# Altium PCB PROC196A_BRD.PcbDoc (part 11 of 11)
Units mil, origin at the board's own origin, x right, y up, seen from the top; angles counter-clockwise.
Board outline 3346.45 x 4921.26 mil, 8 copper layers (Top Layer, GND1, SIG1, PWR1, PWR2, SIG2, GND2, Bottom Layer), stack 54.534 mil thick; 736 components, 498 nets, 3030 pads, 1279 vias.
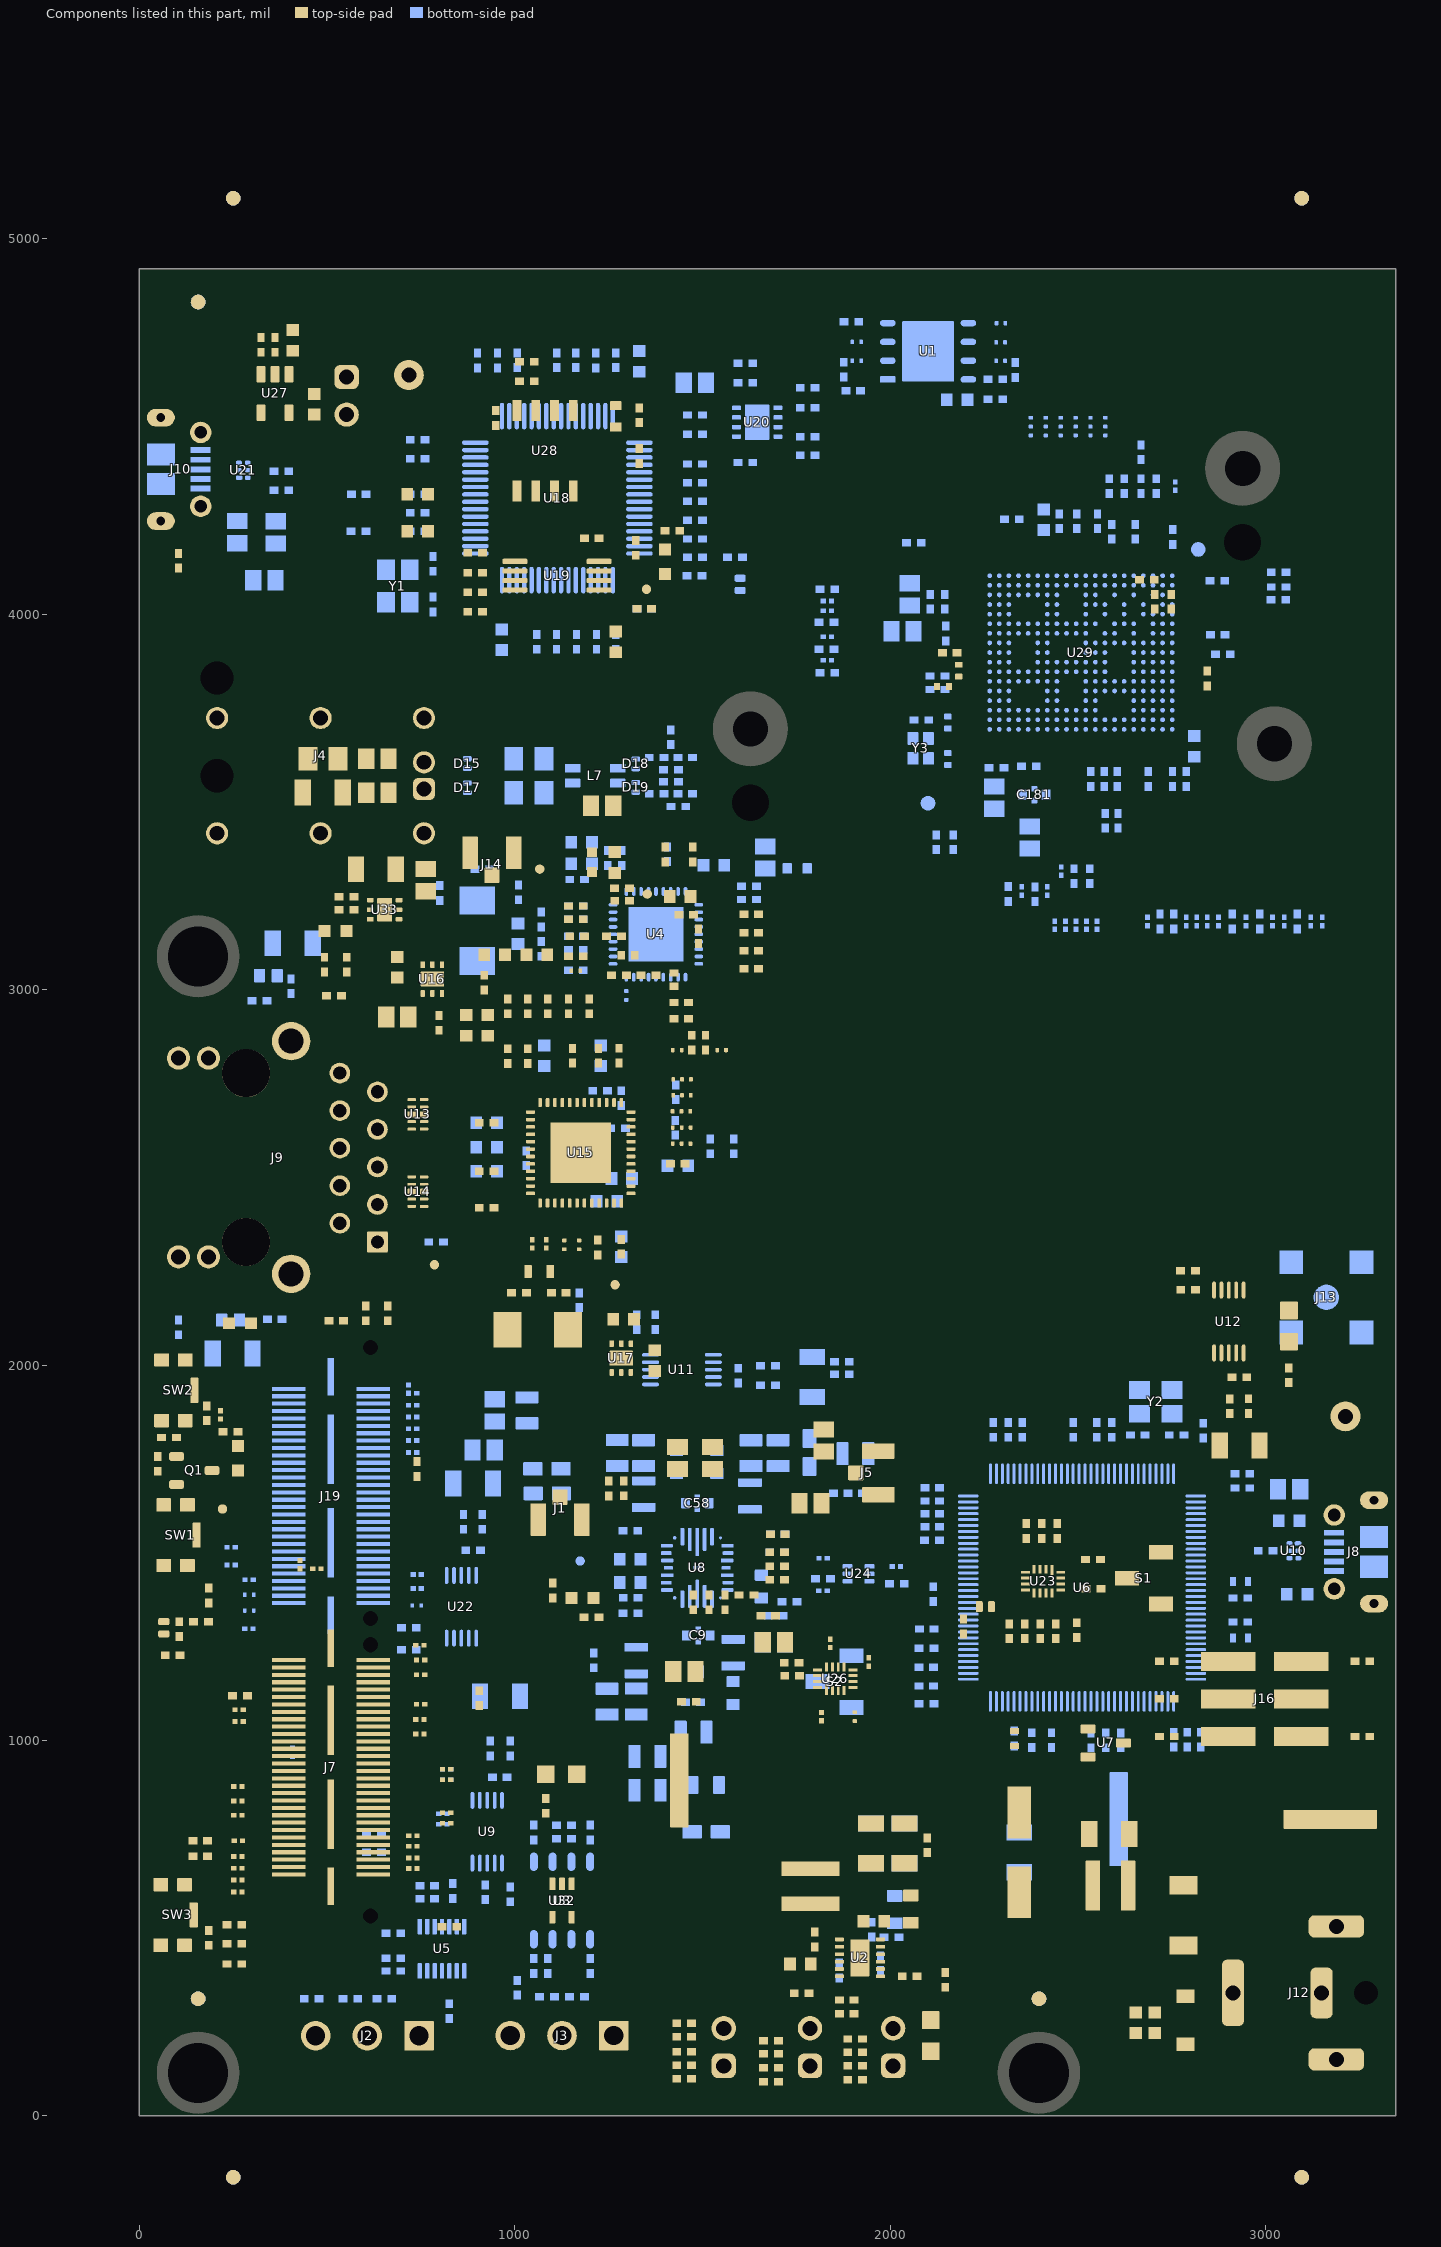
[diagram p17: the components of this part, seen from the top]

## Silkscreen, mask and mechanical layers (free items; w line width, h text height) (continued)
Bottom Overlay:
  circle w15: c2217,3665 r5
  circle w6: c2596.23,1933.67 r13.43
  circle w6: c657.29,3975.77 r13.43
  lines w10: 56.89,712.58 206.89,712.58 ; 56.89,507.81 56.89,1400.46 206.89,1400.46 206.89,507.81 56.89,507.81 ; 435.88,505.37 435.88,1118.29 537.35,1118.29 537.35,505.37 435.88,505.37
  text "FTDI_USB" at 323.96,4664.43 h30
  text "GND" at 786.99,4521.46 h30
  text "SOP4" at 2628.32,3368.81 h35 r270
  text "AUTO_ETH_JACK" at 629.91,3233.93 h30
  text "SOP3" at 2574.25,3225.81 h35
  text "CLKP_SMA" at 3248.2,2398.18 h30
  text "ETH_JACK" at 731.64,2386.93 h30 r270
  text "1V8" at 1833.2,2080.67 h30
  text "MIPI_CONN" at 326.39,1710.87 h30
  text "1V0" at 794.72,1690.41 h30
  text "1V0_FILT" at 986.29,1570.96 h30 r270
  text "XDS_USB" at 3286.71,1270.61 h30
  text "DBG_SPI" at 1974.28,1197.5 h30 r270
  text "1V2" at 832.48,1082.03 h30 r270
  text "SPI_MUX" at 1703,1012.81 h30 r270
  text "PMIC_SPI" at 1995,984.81 h30
  text "GND" at 2760.39,831.57 h30
  text "SL#" at 98.82,532.58 h30 r270
  text "ASSY REV:" at 465.64,527.97 h30 r270
  text "FY23-24/00616000201" at 301.83,458.31 h30 r270
  text "12V, >2.5A" at 2855.61,304.31 h30
  text ".Layer_Name" at 931.33,-846.68 h60
Top Paste:
  text ".Layer_Name" at 931.33,-846.68 h60
Bottom Paste:
  text ".Layer_Name" at 931.33,-846.68 h60
Top Solder:
  text ".Layer_Name" at 931.33,-846.68 h60
  text ".Layer_Name" at 931.33,-846.68 h60
Bottom Solder:
  text ".Layer_Name" at 931.33,-846.68 h60
Drill Guide:
  text ".Layer_Name" at 931.33,-846.68 h60
M1 Board Outline:
  lines w2: 0,0 3346.45,0 ; 0,0 0,-275.59 3346.45,-275.59 3346.45,0 ; 0,0 0,4921.25 ; 0,4921.26 3346.45,4921.26 ; 0,4921.25 0,5196.85 3346.45,5196.85 3346.45,4921.26 ; 3346.45,0 3346.45,4921.25
  text ".Layer_Name" at 468.07,-778 h30
M2 Board Dimensions:
  text ".Layer_Name" at 1011.75,-766.86 h30
M3 3D STEP Top:
  text ".Layer_Name" at 931.33,-846.68 h60
M4 3D STEP Bottom:
  text ".Layer_Name" at 931.33,-846.68 h60
M5 Assembly Top:
  lines w4: 1187.32,3003.74 1187.32,3009.92 1005.63,3009.92 1005.63,2948.6 1005.63,2891.43 1383.3,2891.43 1383.3,3018.25 1242.04,3018.25 1242.04,3012.6 ; 1955.2,51.3 1955.2,226.86 1853.52,226.86 1853.52,50.29 2295.24,50.29 2295.24,291.43 2164.08,291.43 2164.08,51.3 ; 1380.43,69.3 1501.44,69.3 1501.44,469.63 1380.43,469.63 1380.43,446.87 1380.43,69.3
  lines w10: 62.33,-918.36 6662.33,-918.36 ; 62.33,-715.02 6664.33,-715.02 ; 62.33,-511.69 62.33,-1121.69 4067.33,-1121.69 6664.33,-1121.69 6664.33,-511.69 62.83,-511.69 62.83,-1121.69 1638.33,-1121.69 ; 2527.33,-1121.69 2527.33,-511.69 ; 3794.33,-715.02 3794.33,-511.69 ; 4634.33,-715.02 4634.33,-511.69 ; 5256.33,-1128.19 5256.33,-925.36
  text "COMPONENTS MARKED 'DNP' SHOULD NOT BE POPULATED." at 3558.2,-220.46 h60
  text "ASSEMBLY VARIANT:" at 3557.7,-335.96 h60
  text ".VariantName" at 4593.7,-335.96 h60
  text "PCB VIEWED FROM TOP SIDE" at 125.83,-643.86 h60
  text "BOARD #:" at 2602.33,-643.86 h60
  text ".PRJ_Number" at 3147.83,-643.86 h60
  text "REV:" at 3992.33,-643.86 h60
  text ".PCB_Rev" at 4283.83,-643.86 h60
  text "SVN REV:" at 4830.33,-643.86 h60
  text ".VersionControl_RevNumber" at 5336.33,-643.86 h60
  text "TID #:" at 2602.33,-847.19 h60
  text ".TID" at 3147.83,-847.19 h60
  text "PLOT NAME =" at 125.83,-1052.53 h60
  text ".plot_File_Name" at 931.33,-1052.53 h60
  text "GENERATED    :" at 2604.33,-1052.53 h60
  text ".Print_Date" at 3473.83,-1052.53 h60
  text ".Print_Time" at 4202.83,-1052.53 h60
  text "TEXAS INSTRUMENTS" at 5467.33,-1052.53 h60
M6 Assembly Bottom:
  lines w4: 1087.19,738.71 1087.19,712.39 1176.38,712.39 1176.38,874.8 1087.19,874.8 1087.19,740.55
  lines w10: 61.83,-715.52 6663.83,-715.52 ; 63.83,-918.86 6663.83,-918.86 ; 1469.83,-1128.69 1469.83,-925.86 ; 2091.83,-715.52 2091.83,-512.19 ; 2931.83,-715.52 2931.83,-512.19 ; 4198.83,-1122.19 4198.83,-512.19 ; 5087.83,-1122.19 6663.33,-1122.19 6663.33,-512.19 61.83,-512.19 61.83,-1122.19 2658.83,-1122.19 6663.83,-1122.19 6663.83,-512.19
  text "COMPONENTS MARKED 'DNP' SHOULD NOT BE POPULATED." at 6456.33,-306.19 h60
  text ".VariantName" at 5412.33,-422.19 h60
  text "ASSEMBLY VARIANT:" at 6451.33,-422.19 h60
  text ".VersionControl_RevNumber" at 1389.83,-644.36 h60
  text "SVN REV:" at 1895.83,-644.36 h60
  text ".PCB_Rev" at 2442.33,-644.36 h60
  text "REV:" at 2733.83,-644.36 h60
  text ".PRJ_Number" at 3578.33,-644.36 h60
  text "BOARD #:" at 4123.83,-644.36 h60
  text "PCB VIEWED FROM BOTTOM SIDE" at 6600.33,-644.36 h60
  text ".TID" at 3578.33,-847.69 h60
  text "TID #:" at 4123.83,-847.69 h60
  text "TEXAS INSTRUMENTS" at 1258.83,-1053.03 h60
  text ".Print_Time" at 2523.33,-1053.03 h60
  text ".Print_Date" at 3252.33,-1053.03 h60
  text "GENERATED    :" at 4121.83,-1053.03 h60
  text ".plot_File_Name" at 5794.83,-1053.03 h60
  text "PLOT NAME =" at 6600.33,-1053.03 h60
M9 Title Sheet:
  drawing of 57 lines, arcs and shapes, not listed
  text "1" at 694.17,8048.31 h70
  text "2" at 3189.83,8048.31 h70
  text "3" at 5679.17,8048.31 h70
  text "4" at 8185.84,8048.31 h70
  text "5" at 10684.83,8048.31 h70
  text "6" at 13189.83,8048.31 h70
  text "A" at -462.17,6905.31 h70
  text "A" at 14337.83,6905.31 h70
  text "B" at -462.17,4525.31 h70
  text "B" at 14337.83,4525.31 h70
  text "C" at -462.17,2150.31 h70
  text "C" at 14337.83,2150.31 h70
  text "PROJECT TITLE:" at 11297.83,289.31 h45
  text "AWR2E44PEVM" at 11347.83,155.98 h70
  text "DESIGNED FOR:" at 11297.83,-11.69 h45
  text ".PRJ_Customer" at 11347.83,-151.69 h70
  text "D" at -462.17,-219.69 h70
  text "D" at 14337.83,-219.69 h70
  text "FILE NAME:" at 11297.83,-311.69 h45
  text ".PCB_File_Name_No_Path" at 11347.83,-431.69 h70
  text "Texas Instruments (TI) and/or its licensors do not warrant the accuracy or completeness of this specification" at 6328.33,-593.53 h45
  text "ENGINEER:" at 11297.83,-601.69 h45
  text "LAYOUT BY:" at 12802.83,-601.69 h45
  text "or any information contained therein. TI and/or its licensors do not warrant that this design will meet" at 6283.34,-706.19 h45
  text "MISTRAL" at 12853.33,-756.68 h70
  text "the specifications, will be suitable for your application or fit for any particular purpose, or will operate in" at 6283.34,-818.86 h45
  text "ALTIUM DESIGNER VERSION:" at 12802.83,-911.69 h45
  text "an implementation. TI and/or its licensors do not warrant that the design is production worthy. You should" at 6283.34,-931.52 h45
  text "completely validate and test your design implementation to confirm the system functionality for your application." at 6328.33,-1044.19 h45
  text ".print_Scale" at 11347.83,-1045.02 h70
  text ".Application_BuildNumber" at 12853.33,-1045.02 h70
  text "1" at 694.17,-1251.69 h70
  text "2" at 3189.83,-1251.69 h70
  text "3" at 5679.17,-1251.69 h70
  text "4" at 8185.84,-1251.69 h70
  text "5" at 10684.83,-1251.69 h70
  text "6" at 13189.83,-1251.69 h70
M10 Fab Notes:
  drawing of 259 lines, arcs and shapes, not listed
  text "DESIGN INFORMATION" at 12336.35,6367.98 h60
  text "MIN. TRACK WIDTH:" at 11691.79,6235.86 h60
  text "4" at 12788.03,6235.86 h60
  text "MIL" at 12942.79,6235.86 h60
  text "3.7" at 12734.95,6114.9 h60
  text "MIN. CLEARANCE:" at 11691.79,6111.73 h60
  text "MIL" at 12940,6111.81 h60
  text "10" at 12771.94,5990 h60
  text "MIN. VIA PAD SIZE:" at 11691.79,5987.61 h60
  text "MIL" at 12942.79,5987.61 h60
  text "MINIMUM ANNULAR RING" at 11327.35,5859.09 h60
  text "0.1mm (3.9MIL)" at 12386.79,5857.71 h60
  text "EXTERNAL" at 13140,5851.81 h60
  text "PER" at 11562.56,5739.36 h60
  text "IPC-D-275 CLASS 2 LEVEL C" at 11782.56,5739.35 h60
  text "MIL, HOLES" at 13270.79,5638.88 h60
  text "+/-" at 12878.33,5630.29 h60
  text "+/-" at 13732.33,5630.29 h60
  text "REGISTRATION TOLERANCES:" at 11362.56,5629.23 h60
  text "METAL" at 12562.33,5629.23 h60
  text "2" at 13138.53,5629.23 h60
  text "3" at 13971.53,5629.23 h60
  text "MIL" at 14087.79,5629.23 h60
  text "HOLE SIZE TOLERANCE (UNLESS OTHERWISE SPECIFIED):" at 11362.56,5530.91 h60
  text "+/-" at 13732.33,5528.04 h60
  text "3" at 13971.53,5526.98 h60
  text "MIL" at 14087.79,5526.98 h60
  text "MATERIAL:" at 11287.79,5389.33 h60
  text "FR-4 High Tg" at 12274.23,5260.81 h60
  text "X" at 12133,5256 h60
  text "FR-408" at 11708.79,5248.3 h60
  text "OTHER" at 13196.79,5248.3 h60
  text "64 MIL (1.63mm) +/-10%" at 12028.89,5105.27 h60
  text ".Total_Thickness" at 13606.73,5101.63 h50
  text "X" at 13190.46,5101 h60
  text "THICKNESS:" at 11362.56,5097.05 h60
  text "OTHER" at 13313.79,5097.05 h60
  text "+/-10%" at 13940.56,5093.91 h50
  text "TOLERANCE:" at 11362.56,4958.73 h60
  text "X" at 12210.79,4958.73 h60
  text "ANSI IPC-6012 TYPE 3 CLASS 2" at 12388.81,4958.73 h60
  text "OTHER +/-" at 12388.79,4814.54 h60
  text "BOW & TWIST:" at 11362.56,4669.35 h60
  text "X" at 12210.79,4669.35 h60
  text "ANSI IPC-6012 TYPE 3 CLASS 2" at 12388.81,4669.35 h60
  text "OTHER +/-" at 12388.79,4522.66 h60
  text "DRILLING:" at 11287.79,4392.04 h60
  text "NC_DRILL FILES" at 13048.79,4286.85 h60
  text "REFERENCE:" at 11362.56,4282.91 h60
  text "X" at 12019.79,4282.82 h60
  text "AS SHOWN" at 12197.79,4282.91 h60
  text "X" at 12920.79,4282.91 h60
  text "OTHER" at 13346.79,4140.66 h60
  text "PTH COPPER THICKNESS:" at 11362.24,4137.13 h60
  text "X" at 12501.47,4137.13 h60
  text "20-30 um" at 12629.47,4137.13 h60
  text "BOARD FINISH:" at 11287.79,3989.54 h60
  text "SILKSCREEN:" at 11443.01,3879.41 h60
  text "X" at 12400.79,3879.41 h60
  text "TOP" at 12517.79,3879.41 h60
  text "X" at 12910.79,3879.41 h60
  text "BOTTOM" at 13028.79,3879.41 h60
  text "SILKSCREEN COLOR:" at 11443.01,3724.22 h60
  text "X" at 12399.79,3724.22 h60
  text "WHITE" at 12517.79,3724.22 h60
  text "OTHER" at 13028.79,3724.22 h60
  text "RED" at 13755.79,3588.91 h60
  text "X" at 13124.17,3583.09 h60
  text "GREEN" at 12648.79,3580.77 h60
  text "OTHER" at 13266.79,3580.77 h60
  text "SOLDER RESIST COLOR:" at 11443.01,3573.91 h60
  text "X" at 12530.79,3426.52 h60
  text "MATTE" at 12648.79,3426.52 h60
  text "SEMI-GLOSS" at 13266.33,3425.88 h60
  text "IMMERSION GOLD (ENIG)" at 12348.79,3253.75 h60
  text "X" at 12170,3246.47 h60
  text "ENEPIG" at 13686.33,3246.53 h60
  text "SURFACE FINISH:" at 11287.79,3245.53 h60
  text "IMM. TIN/SILVER OR EQUIV" at 11617.33,3108.21 h60
  text "OTHER" at 13048.79,3104.28 h60
  text "ARRAY/PANEL:" at 11287.79,2948.9 h60
  text "CUT AND TRIM PER M1 BOARD OUTLINE" at 12348.79,2940.68 h60
  text "NOTES : UNLESS OTHERWISE SPECIFIED." at 5648.26,2857.61 h60
  text "X" at 13035,2806.81 h60
  text "N.C. ROUTE" at 12348.79,2804.71 h60
  text "V. SCORE" at 13214.79,2804.71 h60
  text "1. FABRICATE PER IPC-6012A CLASS 2." at 5795.53,2709.61 h60
  text "CERTIFICATION:" at 11287.79,2675.58 h60
  text "MATERIALS AND WORKMANSHIP FOR ALL PCBS" at 12012.79,2675.58 h60
  text "2. FOR IMPEDANCE DETAILS REFER STACKUP & IMPEDANCE TABLE." at 5795.53,2589.61 h60
  text "TO MEET OR EXCEED THE REQUIREMENTS OF:" at 12012.79,2581.52 h60
  text "3. PRINTED WIRING BOARD SHALL COMPLY WITH REQUIREMENTS OF ANSI/J-STD-003." at 5795.53,2469.61 h60
  text "X" at 11650.3,2452.89 h60
  text "ANSI IPC-A-600F CLASS ->" at 11778.29,2452.89 h60
  text "X" at 13426.3,2452.89 h60
  text "2" at 13536.29,2452.89 h60
  text "1" at 13221.29,2451.39 h60
  text "3" at 13890.29,2451.39 h60
  text "4. SURFACE FINISH: ENIG" at 5795.53,2349.61 h60
  text "X" at 12462.3,2305.2 h60
  text "RoHS" at 12590.29,2305.2 h60
  text "OTHER" at 13234.69,2305.2 h60
  text "PER ORDER" at 13631.75,2305.2 h60
  text "5. SOLDERMASK ON BOTH SIDES OF THE BOARD SHALL BE LPI, COLOR RED." at 5795.53,2229.61 h60
  text "ALL BOARDS MUST MEET OR EXCEED UL94-V0 REQUIREMENTS." at 11315.33,2151.38 h60
  text "6. SILK SCREEN LEGEND TO BE APPLIED PER LAYER STACKUP USING WHITE" at 5795.53,2109.61 h60
  text "PCB MUST BEAR THE UL94V-0 UL REGISTERED MATERIAL ID NUMBER" at 11315.33,2035.31 h60
  text "NON-CONDUCTIVE EPOXY INK." at 5917.63,2009.61 h60
  text "7. THIS PRINTED WIRING BOARD IS DESIGNED WITH A MINIMUM CONDUCTOR" at 5795.53,1909.61 h60
  text "ADDITIONAL REQUIREMENTS:" at 11287.79,1865.89 h60
  text "WIDTH AND SPACING OF 4 MIL &  3.7 MILS." at 5917.63,1809.61 h60
  text "MICROSECTION:" at 11362.56,1758.76 h60
  text "YES" at 12268.29,1758.76 h60
  text "8. ALL VIAS ARE TENTED ON BOTH SIDES UNLESS SOLDERMASK OPENED IN GERBER." at 5795.53,1709.61 h60
  text "REQUIRED" at 13129.79,1614.43 h60
  text "BARE BOARD ELEC. TEST:" at 11362.56,1611.57 h60
  text "NONE" at 12668.29,1611.57 h60
  text "X" at 13011.79,1611.57 h60
  text "PER ORDER" at 13721.79,1611.57 h60
  text "9. ALL VIAS SHOULD BE FILLED WITH NON CONDUCTIVE EPOXY AND SURFACE SHOULD BE FLAT AND CAP PLATED" at 5795.53,1609.61 h60
  text "10. VENDOR SHOULD FOLLOW ROHS COMPLIANT PROCESS AND Pb FREE FOR MANUFACTURING" at 5755.64,1468.15 h60
  text "X" at 11414.11,1464.29 h60
  text "8 & 10 MIL VIAS REQUIRE NON-CONDUCTIVE FILL AND PLANARIZE" at 11551.06,1396.93 h59
  text "11. MANUFACTURER'S IDENTIFICATION, DATECODE LETTER SHALL BE SILKSCREENED ON SOLDER SIDE OF THE BOARD" at 5755.64,1348.15 h60
  text "XX MIL VIAS REQUIRE CONDUCTIVE FILL AND PLANARIZE" at 11538.71,1302.65 h60
  text "12. BOARD DIMENSIONS ARE IN MM." at 5748.07,1213.38 h60
  text "BOARD IMPEDANCE SHALL BE FOLLOWED AS PER THE" at 11560,1168.81 h58
  text "X" at 11421.11,1137.51 h60
  text "13. BOW AND TWIST SHALL NOT EXCEED 0.7% OF LONGEST SIDE" at 5748.07,1073.38 h60
  text "IMPEDANCE SPECIFICATION TABLE." at 11552,1070.81 h58
  text "14. TEAR DROPS SHALL BE ADDED ON INTERNAL AND EXTERNAL LAYER FOR ALL THE VIA'S AND THROUGH HOLE PADS." at 5747.64,938.64 h60
  text "15. PCB Material must meet or exceed UL94V-0 requirements." at 5748.07,783.38 h60
  text "R 0.20(mm)" at 4775.17,750.81 h60
  text "R 0.30(mm)" at 4775.17,649.81 h60
  text "PCB must bear the UL94V-0 registered material ID number." at 5910.17,643.38 h60
  text "16. LAYER TO LAYER REGISTRATION SHALL BE WITHIN +/-2 MIL" at 5748.07,503.38 h60
  text "17. BOARD SHALL HAVE THE CUTOUTS AS INDICATED." at 5765.96,373.13 h60
  text "18. THE DETAIL \"A\" CUTOUT SHALL FOLLOW BELOW INSTRUCTIONS." at 5764.69,205.22 h60
  text "1.13(mm)" at 3912.93,180.81 h60 r90
  text "0.50(mm)" at 4863.17,180.81 h60 r90
  text "1.78(mm)" at 4625.17,59.81 h60
  text "0.27(mm)" at 4625.17,-83.19 h60
  text "A) INDICATED DIMENSIONS ON DETAIL \"A\" IS FINISHED AFTER PLATING. TOLERANCE AFTER PLATING SHALL BE WITHIN +/- 0.05MM" at 5919.58,-149 h60
  text "19. INDICATED CUTOUT DETAILS ARE MEASURED AFTER PLATING AND DATA SHALL BE PROVIDED ALONG WITH THE COC" at 5768.14,-277.48 h60
  text "CUTOUT DETAIL - \"A\"" at 3703.35,-306.32 h100
  text "20. ALL UNCONNECTED VIA'S SHALL BE SUPPRESSED." at 5768.14,-419.65 h60
  text ".Layer_Name" at 931.33,-846.68 h60
M11 Gerber Information:
  lines w10: -337.67,-918.36 6262.33,-918.36 ; -337.67,-715.02 6264.33,-715.02 ; -337.67,-511.69 -337.67,-1121.69 3667.33,-1121.69 6264.33,-1121.69 6264.33,-511.69 -337.17,-511.69 -337.17,-1121.69 1238.33,-1121.69 ; 2127.33,-1121.69 2127.33,-511.69 ; 3394.33,-715.02 3394.33,-511.69 ; 4234.33,-715.02 4234.33,-511.69 ; 4856.33,-1128.19 4856.33,-925.36
  text "ALL ARTWORK VIEWED FROM TOP SIDE" at -274.17,-643.86 h60
  text "BOARD #:" at 2202.33,-643.86 h60
  text ".PRJ_Number" at 2747.83,-643.86 h60
  text "REV:" at 3592.33,-643.86 h60
  text ".PCB_Rev" at 3883.83,-643.86 h60
  text "SVN REV:" at 4430.33,-643.86 h60
  text ".VersionControl_RevNumber" at 4936.33,-643.86 h60
  text "LAYER NAME =" at -274.17,-846.68 h60
  text "TID #:" at 2202.33,-847.19 h60
  text ".TID" at 2747.83,-847.19 h60
  text "PLOT NAME =" at -274.17,-1052.53 h60
  text ".plot_File_Name" at 531.33,-1052.53 h60
  text "GENERATED    :" at 2204.33,-1052.53 h60
  text ".Print_Date" at 3073.83,-1052.53 h60
  text ".Print_Time" at 3802.83,-1052.53 h60
  text "TEXAS INSTRUMENTS" at 5067.33,-1052.53 h60
M12 Stackup:
  drawing of 772 lines, arcs and shapes, not listed
  text "2" at -107.21,7677.95 h100
  text "IMPEDANCE SPECIFICATIONS" at 71.77,7657.61 h100
  text "IMPEDANCE SPECIFICATIONS" at 71.77,7657.61 h100
  text "SL#" at -63.23,7307.61 h100
  text "SL#" at -63.23,7307.61 h100
  text "TYPE" at 1321.77,7307.61 h100
  text "TYPE" at 1321.77,7307.61 h100
  text "LAYER" at 2781.77,7307.61 h100
  text "LAYER" at 2781.77,7307.61 h100
  text "TRACEWIDTH(Mils)" at 3616.77,7307.61 h100
  text "TRACEWIDTH(Mils)" at 3616.77,7307.61 h100
  text "SPACING(Mils)" at 5261.77,7307.61 h100
  text "SPACING(Mils)" at 5261.77,7307.61 h100
  text "IMPEDANCE(Ohms)" at 6576.77,7307.61 h100
  text "IMPEDANCE(Ohms)" at 6576.77,7307.61 h100
  text "REF LAYER" at 8196.77,7307.61 h100
  text "REF LAYER" at 8196.77,7307.61 h100
  text "---" at 5645.79,7091.95 h100
  text "L1" at 2906.37,7090.95 h100
  text "L02" at 8358.78,7090.95 h100
  text "8" at 4093.76,7081.61 h100
  text "50" at 7093.76,7078.61 h100
  text "01" at -19.21,7074.95 h100
  text "MICROSTRIP" at 324.36,7067.02 h100
  text "4.55" at 5665.79,6912.95 h100
  text "EDGE COUPLED MICROSTRIP" at 325.87,6906.75 h100
  text "5.65" at 3991.64,6906.61 h100
  text "L1" at 2906.37,6905.95 h100
  text "90" at 7093.76,6903.61 h100
  text "L02" at 8358.78,6903.95 h100
  text "02" at -23.03,6895.94 h100
  text "L02" at 8358.78,6733.95 h100
  text "EDGE COUPLED MICROSTRIP" at 325.87,6732.38 h100
  text "4.8" at 4033.54,6731.61 h100
  text "L1" at 2906.37,6730.95 h100
  text "100" at 7057.1,6728.61 h100
  text "5.4" at 5707.92,6722.95 h100
  text "03" at -23.03,6720.94 h100
  text "EDGE COUPLED STRIPLINE" at 325.53,6560.66 h100
  text "L02/L04,L05/L07" at 7921.49,6560.81 h100
  text "L3, L6" at 2753.79,6557.39 h100
  text "7.2" at 5710.3,6548.47 h100
  text "04" at -23.03,6545.94 h100
  text "4.8" at 4033.54,6546.08 h100
  text "100" at 7057.1,6545.74 h100
  text "STRIPLINE" at 323.27,6385.44 h100
  text "L3, L6" at 2753.79,6385.12 h100
  text "6" at 4096.14,6379.95 h100
  text "50" at 7093.76,6378.61 h100
  text "L02/L04,L05,L07" at 7942.44,6378.61 h100
  text "---" at 5645.79,6376.35 h100
  text "05" at -23.03,6370.94 h100
  text "---" at 5645.79,6213.46 h100
  text "L8" at 2884.95,6212.46 h100
  text "8" at 4093.76,6212.36 h100
  text "L07" at 8358.78,6212.46 h100
  text "50" at 7093.76,6200.13 h100
  text "06" at -23.03,6195.94 h100
  text "MICROSTRIP" at 308.77,6188.53 h100
  text "4.55" at 5665.79,6037.95 h100
  text "EDGE COUPLED MICROSTRIP" at 325.87,6031.75 h100
  text "5.65" at 3991.64,6031.61 h100
  text "L8" at 2884.95,6030.95 h100
  text "90" at 7093.76,6028.61 h100
  text "L07" at 8358.78,6028.95 h100
  text "07" at -13.22,6023.78 h100
  text "L07" at 8358.78,5858.95 h100
  text "EDGE COUPLED MICROSTRIP" at 325.87,5857.38 h100
  text "4.8" at 4033.54,5856.61 h100
  text "L8" at 2884.95,5855.95 h100
  text "100" at 7057.1,5853.61 h100
  text "08" at -19.21,5849.95 h100
  text "5.4" at 5707.92,5847.95 h100
  text "6.2" at 5712.92,5687.95 h100
  text "EDGE COUPLED STRIPLINE" at 325.87,5682.38 h100
  text "5.8" at 4033.54,5681.61 h100
  text "L6" at 2887.33,5680.95 h100
  text "90" at 7093.76,5678.61 h100
  text "L07" at 8358.78,5678.95 h100
  text "09" at -19.21,5674.95 h100
  text "EDGE COUPLED MICROSTRIP" at 338.65,5508.38 h100
  text "10" at -22.16,5507.94 h100
  text "L07" at 8262.57,5506.94 h100
  text "4" at 4176.55,5501.6 h100
  text "L8" at 2773.57,5500.94 h100
  text "120" at 7113.55,5498.6 h100
  text "9.5" at 5681.57,5494.94 h100
  text "THIS IS AN IMPEDANCE CONTROLLED BOARD." at 4405.44,5157 h75
  text "NOTE :" at 3973.54,5136.48 h75
  text "EXTERNAL LAYER CU THICKNESSES ARE FINISHED THICKNESS AFTER PLATING." at 3974.77,5007.95 h75
  text "2" at 4596.52,4717.06 h100
  text "LAYER STACKUP" at 4760.51,4702.72 h100
  text "LAYER STACKUP" at 4760.51,4702.72 h100
  text "Layer" at 4593.71,4518.44 h35.86
  text "Name" at 4846.72,4518.44 h35.86
  text "Material" at 5410.37,4518.44 h35.86
  text "Thickness" at 5932.2,4518.44 h35.86
  text "Constant" at 6328.58,4518.44 h35.86
  text "Board Layer Stack" at 6989.92,4518.44 h35.86
  text "Top Overlay" at 4846.72,4446.73 h35.86
  text "Top Solder" at 4846.72,4375.02 h35.86
  text "Solder Resist" at 5410.37,4375.02 h35.86
  text "1.00mil" at 5932.2,4375.02 h35.86
  text "3.5" at 6328.58,4375.02 h35.86
  text "1" at 4593.71,4303.31 h35.86
  text "Top Layer" at 4846.72,4303.31 h35.86
  text "1.85mil" at 5932.2,4303.31 h35.86
  text "Dielectric 1" at 4846.72,4231.6 h35.86
  text "FR-4 High Tg" at 5410.37,4231.6 h35.86
  text "4.40mil" at 5932.2,4231.6 h35.86
  text "3.54" at 6328.58,4231.6 h35.86
  text "2" at 4593.71,4159.89 h35.86
  text "GND1" at 4846.72,4159.89 h35.86
  text "1.26mil" at 5932.2,4159.89 h35.86
  text "Dielectric 2" at 4846.72,4088.18 h35.86
  text "FR-4 High Tg" at 5410.37,4088.18 h35.86
  text "5.00mil" at 5932.2,4088.18 h35.86
  text "3.88" at 6328.58,4088.18 h35.86
  text "3" at 4593.71,4016.47 h35.86
  text "SIG1" at 4846.72,4016.47 h35.86
  text "0.69mil" at 5932.2,4016.47 h35.86
  text "Dielectric 3" at 4846.72,3944.76 h35.86
  text "FR-4 High Tg" at 5410.37,3944.76 h35.86
  text "10.31mil" at 5932.2,3944.76 h35.86
  text "3.86" at 6328.58,3944.76 h35.86
  text "4" at 4593.71,3873.05 h35.86
  text "PWR1" at 4846.72,3873.05 h35.86
  text "1.26mil" at 5932.2,3873.05 h35.86
  text "Dielectric 4" at 4846.72,3801.34 h35.86
  text "FR-4 High Tg" at 5410.37,3801.34 h35.86
  text "5.00mil" at 5932.2,3801.34 h35.86
  text "3.88" at 6328.58,3801.34 h35.86
  text "5" at 4593.71,3729.63 h35.86
  text "PWR2" at 4846.72,3729.63 h35.86
  text "1.26mil" at 5932.2,3729.63 h35.86
  text "Dielectric 5" at 4846.72,3657.91 h35.86
  text "FR-4 High Tg" at 5410.37,3657.91 h35.86
  text "10.31mil" at 5932.2,3657.91 h35.86
  text "3.86" at 6328.58,3657.91 h35.86
  text "6" at 4593.71,3586.2 h35.86
  text "SIG2" at 4846.72,3586.2 h35.86
  text "0.69mil" at 5932.2,3586.2 h35.86
  text "Dielectric 6" at 4846.72,3514.49 h35.86
  text "FR-4 High Tg" at 5410.37,3514.49 h35.86
  text "5.00mil" at 5932.2,3514.49 h35.86
  text "3.88" at 6328.58,3514.49 h35.86
  text "7" at 4593.71,3442.78 h35.86
  text "GND2" at 4846.72,3442.78 h35.86
  text "1.26mil" at 5932.2,3442.78 h35.86
  text "Dielectric 7" at 4846.72,3371.07 h35.86
  text "FR-4 High Tg" at 5410.37,3371.07 h35.86
  text "4.40mil" at 5932.2,3371.07 h35.86
  text "3.54" at 6328.58,3371.07 h35.86
  text "8" at 4593.71,3299.36 h35.86
  text "Bottom Layer" at 4846.72,3299.36 h35.86
  text "1.85mil" at 5932.2,3299.36 h35.86
  text "Bottom Solder" at 4846.72,3227.65 h35.86
  text "Solder Resist" at 5410.37,3227.65 h35.86
  text "1.00mil" at 5932.2,3227.65 h35.86
  text "3.5" at 6328.58,3227.65 h35.86
  text "Bottom Overlay" at 4846.72,3155.94 h35.86
  text ".Layer_Name" at 1011.22,-901.31 h30
M13 Component Bodies Top:
  text ".Layer_Name" at 931.33,-846.68 h60
M14 Component Bodies Bottom:
  text ".Layer_Name" at 931.33,-846.68 h60
M15 Courtyards Top:
  text ".Layer_Name" at 931.33,-846.68 h60
M16 Courtyards Bottom:
  text ".Layer_Name" at 931.33,-846.68 h60
Drill Drawing:
  drawing of 180 lines, arcs and shapes, not listed
  text "Symbol" at -385.73,12461.99 h72
  text "Count" at 120.14,12461.99 h72
  text "Hole Size" at 769.97,12461.99 h72
  text "Hole Length" at 1919.63,12461.99 h72
  text "Plated" at 2989.32,12461.99 h72
  text "Hole Type" at 3495.2,12461.99 h72
  text "Drill Layer Pair" at 4229,12461.99 h72
  text "Via/Pad" at 5728.55,12461.99 h72
  text "Pad Shape" at 6318.4,12461.99 h72
  text "Hole Tolerance (+)" at 7408.08,12461.99 h72
  text "Hole Tolerance (-)" at 8741.69,12461.99 h72
  text "1" at 120.14,12311.99 h60
  text "62.99mil (1.600mm)" at 769.97,12311.99 h60
  text "-" at 1919.63,12311.99 h60
  text "NPTH" at 2989.32,12311.99 h60
  text "Round" at 3495.2,12311.99 h60
  text "Top Layer - Bottom Layer" at 4229,12311.99 h60
  text "Pad" at 5728.55,12311.99 h60
  text "Rounded" at 6318.4,12311.99 h60
  text "3.94mil (0.100mm)" at 7408.08,12311.99 h60
  text "0.00mil (0.000mm)" at 8741.69,12311.99 h60
  text "2" at 120.14,12161.99 h60
  text "66.93mil (1.700mm)" at 769.97,12161.99 h60
  text "-" at 1919.63,12161.99 h60
  text "PTH" at 2989.32,12161.99 h60
  text "Round" at 3495.2,12161.99 h60
  text "Top Layer - Bottom Layer" at 4229,12161.99 h60
  text "Pad" at 5728.55,12161.99 h60
  text "Rounded" at 6318.4,12161.99 h60
  text "2" at 120.14,12011.99 h60
  text "88.58mil (2.250mm)" at 769.97,12011.99 h60
  text "-" at 1919.63,12011.99 h60
  text "NPTH" at 2989.32,12011.99 h60
  text "Round" at 3495.2,12011.99 h60
  text "Top Layer - Bottom Layer" at 4229,12011.99 h60
  text "Pad" at 5728.55,12011.99 h60
  text "Rounded" at 6318.4,12011.99 h60
  text "E" at -414.82,12002 h66.67
  text "2" at 120.14,11861.99 h60
  text "98.00mil (2.489mm)" at 769.97,11861.99 h60
  text "-" at 1919.63,11861.99 h60
  text "NPTH" at 2989.32,11861.99 h60
  text "Round" at 3495.2,11861.99 h60
  text "Top Layer - Bottom Layer" at 4229,11861.99 h60
  text "Pad" at 5728.55,11861.99 h60
  text "Rounded" at 6318.4,11861.99 h60
  text "2.00mil (0.051mm)" at 7408.08,11861.99 h60
  text "2.00mil (0.051mm)" at 8741.69,11861.99 h60
  text "G" at -414.82,11852 h66.67
  text "2" at 120.14,11711.99 h60
  text "127.95mil (3.250mm)" at 769.97,11711.99 h60
  text "-" at 1919.63,11711.99 h60
  text "NPTH" at 2989.32,11711.99 h60
  text "Round" at 3495.2,11711.99 h60
  text "Top Layer - Bottom Layer" at 4229,11711.99 h60
  text "Pad" at 5728.55,11711.99 h60
  text "Rounded" at 6318.4,11711.99 h60
  text "3" at 120.14,11561.99 h60
  text "94.02mil (2.388mm)" at 769.97,11561.99 h60
  text "-" at 1919.63,11561.99 h60
  text "PTH" at 2989.32,11561.99 h60
  text "Round" at 3495.2,11561.99 h60
  text "Top Layer - Bottom Layer" at 4229,11561.99 h60
  text "Pad" at 5728.55,11561.99 h60
  text "Rounded" at 6318.4,11561.99 h60
  text "2.00mil (0.051mm)" at 7408.08,11561.99 h60
  text "2.00mil (0.051mm)" at 8741.69,11561.99 h60
  text "H" at -414.82,11552 h66.67
  text "3" at 120.14,11411.99 h60
  text "160.00mil (4.064mm)" at 769.97,11411.99 h60
  text "-" at 1919.63,11411.99 h60
  text "PTH" at 2989.32,11411.99 h60
  text "Round" at 3495.2,11411.99 h60
  text "Top Layer - Bottom Layer" at 4229,11411.99 h60
  text "Pad" at 5728.55,11411.99 h60
  text "Rounded" at 6318.4,11411.99 h60
  text "4" at 120.14,11261.99 h60
  text "23.62mil (0.600mm)" at 769.97,11261.99 h60
  text "51.18mil (1.300mm)" at 1919.63,11261.99 h60
  text "PTH" at 2989.32,11261.99 h60
  text "Slot" at 3495.2,11261.99 h60
  text "Top Layer - Bottom Layer" at 4229,11261.99 h60
  text "Pad" at 5728.55,11261.99 h60
  text "Rounded" at 6318.4,11261.99 h60
  text "4" at 120.14,11111.99 h60
  text "33.47mil (0.850mm)" at 769.97,11111.99 h60
  text "-" at 1919.63,11111.99 h60
  text "PTH" at 2989.32,11111.99 h60
  text "Round" at 3495.2,11111.99 h60
  text "Top Layer - Bottom Layer" at 4229,11111.99 h60
  text "Pad" at 5728.55,11111.99 h60
  text "Rounded" at 6318.4,11111.99 h60
  text "4" at 120.14,10961.99 h60
  text "39.37mil (1.000mm)" at 769.97,10961.99 h60
  text "(Mixed)" at 1919.63,10961.99 h60
  text "PTH" at 2989.32,10961.99 h60
  text "Rectangle" at 3495.2,10961.99 h60
  text "Top Layer - Bottom Layer" at 4229,10961.99 h60
  text "Pad" at 5728.55,10961.99 h60
  text "Rounded Rectangle" at 6318.4,10961.99 h60
  text "4" at 120.14,10811.99 h60
  text "40.16mil (1.020mm)" at 769.97,10811.99 h60
  text "-" at 1919.63,10811.99 h60
  text "NPTH" at 2989.32,10811.99 h60
  text "Round" at 3495.2,10811.99 h60
  text "Top Layer - Bottom Layer" at 4229,10811.99 h60
  text "Pad" at 5728.55,10811.99 h60
  text "Rounded" at 6318.4,10811.99 h60
  text "4" at 120.14,10661.99 h60
  text "40.16mil (1.020mm)" at 769.97,10661.99 h60
  text "-" at 1919.63,10661.99 h60
  text "PTH" at 2989.32,10661.99 h60
  text "Round" at 3495.2,10661.99 h60
  text "Top Layer - Bottom Layer" at 4229,10661.99 h60
  text "Pad" at 5728.55,10661.99 h60
  text "Rounded" at 6318.4,10661.99 h60
  text "6" at 120.14,10511.99 h60
  text "51.18mil (1.300mm)" at 769.97,10511.99 h60
  text "-" at 1919.63,10511.99 h60
  text "PTH" at 2989.32,10511.99 h60
  text "Round" at 3495.2,10511.99 h60
  text "Top Layer - Bottom Layer" at 4229,10511.99 h60
  text "Pad" at 5728.55,10511.99 h60
  text "(Mixed)" at 6318.4,10511.99 h60
  text "B" at -414.82,10502 h66.67
  text "7" at 120.14,10361.99 h60
  text "8.00mil (0.203mm)" at 769.97,10361.99 h60
  text "-" at 1919.63,10361.99 h60
  text "PTH" at 2989.32,10361.99 h60
  text "Round" at 3495.2,10361.99 h60
  text "Top Layer - Bottom Layer" at 4229,10361.99 h60
  text "Via" at 5728.55,10361.99 h60
  text "Rounded" at 6318.4,10361.99 h60
  text "F" at -414.82,10352 h66.67
  text "8" at 120.14,10211.99 h60
  text "39.37mil (1.000mm)" at 769.97,10211.99 h60
  text "-" at 1919.63,10211.99 h60
  text "PTH" at 2989.32,10211.99 h60
  text "Round" at 3495.2,10211.99 h60
  text "Top Layer - Bottom Layer" at 4229,10211.99 h60
  text "Pad" at 5728.55,10211.99 h60
  text "(Mixed)" at 6318.4,10211.99 h60
  text "1.97mil (0.050mm)" at 7408.08,10211.99 h60
  text "1.97mil (0.050mm)" at 8741.69,10211.99 h60
  text "D" at -414.82,10202 h66.67
  text "10" at 120.14,10061.99 h60
  text "35.43mil (0.900mm)" at 769.97,10061.99 h60
  text "-" at 1919.63,10061.99 h60
  text "PTH" at 2989.32,10061.99 h60
  text "Round" at 3495.2,10061.99 h60
  text "Top Layer - Bottom Layer" at 4229,10061.99 h60
  text "Pad" at 5728.55,10061.99 h60
  text "(Mixed)" at 6318.4,10061.99 h60
  text "10" at 120.14,9911.99 h60
  text "40.00mil (1.016mm)" at 769.97,9911.99 h60
  text "-" at 1919.63,9911.99 h60
  text "PTH" at 2989.32,9911.99 h60
  text "Round" at 3495.2,9911.99 h60
  text "Top Layer - Bottom Layer" at 4229,9911.99 h60
  text "Pad" at 5728.55,9911.99 h60
  text "(Mixed)" at 6318.4,9911.99 h60
  text "11" at 120.14,9761.99 h60
  text "10.00mil (0.254mm)" at 769.97,9761.99 h60
  text "-" at 1919.63,9761.99 h60
  text "PTH" at 2989.32,9761.99 h60
  text "Round" at 3495.2,9761.99 h60
  text "Top Layer - Bottom Layer" at 4229,9761.99 h60
  text "Via" at 5728.55,9761.99 h60
  text "Rounded" at 6318.4,9761.99 h60
  text "3.00mil (0.076mm)" at 7408.08,9761.99 h60
  text "3.00mil (0.076mm)" at 8741.69,9761.99 h60
  text "32" at 120.14,9611.99 h60
  text "7.87mil (0.200mm)" at 769.97,9611.99 h60
  text "-" at 1919.63,9611.99 h60
  text "PTH" at 2989.32,9611.99 h60
  text "Round" at 3495.2,9611.99 h60
  text "Top Layer - Bottom Layer" at 4229,9611.99 h60
  text "Via" at 5728.55,9611.99 h60
  text "Rounded" at 6318.4,9611.99 h60
  text "1223" at 120.14,9461.99 h60
  text "8.00mil (0.203mm)" at 769.97,9461.99 h60
  text "-" at 1919.63,9461.99 h60
  text "PTH" at 2989.32,9461.99 h60
  text "Round" at 3495.2,9461.99 h60
  text "Top Layer - Bottom Layer" at 4229,9461.99 h60
  text "Via" at 5728.55,9461.99 h60
  text "Rounded" at 6318.4,9461.99 h60
  text "3.00mil (0.076mm)" at 7408.08,9461.99 h60
  text "3.00mil (0.076mm)" at 8741.69,9461.99 h60
  text "A" at -414.82,9452 h66.67
  text "1342 Total" at 120.14,9311.99 h60
  text "Slot definitions :" at -385.73,9167.02 h60
  text "Routed Path Length" at 646.96,9167.02 h60
  text "= Calculated from tool start centre position to tool end centre position." at 1749.62,9167.02 h60
  text "Hole Length" at 646.96,9067.05 h60
  text "= Routed Path Length + Tool Size = Slot length as defined in the PCB layout" at 1339.76,9067.05 h60
  text "Symbol" at -377.09,8843 h72
  text "Count" at 128.78,8843 h72
  text "Hole Size" at 608.66,8843 h72
  text "Hole Length" at 1638.36,8843 h72
  text "Plated" at 2504.12,8843 h72
  text "Hole Type" at 3010,8843 h72
  text "Drill Layer Pair" at 3743.8,8843 h72
  text "Via/Pad" at 4933.46,8843 h72
  text "Pad Shape" at 5523.31,8843 h72
  text "Hole Tolerance (+)" at 6269.1,8843 h72
  text "Hole Tolerance (-)" at 7602.71,8843 h72
  text "6" at 128.78,8693 h60
  text "4.00mil (0.102mm)" at 608.66,8693 h60
  text "-" at 1638.36,8693 h60
  text "PTH" at 2504.12,8693 h60
  text "Round" at 3010,8693 h60
  text "SIG2 - Bottom Layer" at 3743.8,8693 h60
  text "Via" at 4933.46,8693 h60
  text "Rounded" at 5523.31,8693 h60
  text "1.00mil (0.025mm)" at 6269.1,8693 h60
  text "1.00mil (0.025mm)" at 7602.71,8693 h60
  text "6 Total" at 128.78,8543 h60
  text ".Layer_Name" at 468.07,-840.66 h35
Top Overlay Removed:
  text ".Layer_Name" at 931.33,-846.68 h60
samtec_TOP:
  drawing of 5031 lines, arcs and shapes, not listed
  text "1.22 [30.99]" at -271.69,-932.94 h60 r90
AWR2243_TASY:
  drawing of 19703 lines, arcs and shapes, not listed
  text "U2" at 1708.53,2373.44 h59.06 r90
  text "J2" at 2898.82,2253.8 h31.5 r90
  text "Y1" at 1911.75,2068.59 h31.5 r90
  text "C26" at 3229.16,1799.87 h47.24 r180
  text "U11" at 2170.98,1743.18 h25.59 r90
  text "C27" at 3230.36,1656.47 h47.24 r180
  text "U5" at 1483.19,1636.36 h72.83 r90
  text "J3" at 3220.89,737.37 h72.83 r90
  text "SW2" at 1983.28,408.75 h39.37 r90
  text "SW1" at 1761.37,406.48 h39.37 r90
  text "U12" at 2196.76,290.39 h25.59 r90
DCA1000_MH_J7:
  drawing of 6645 lines, arcs and shapes, not listed
  text "ASSEMBLY TOP" at 696.78,4610.32 h100
DogBone Cutout DXF:
  drawing of 1320 lines, arcs and shapes, not listed
Waveguide DXF:
  drawing of 307 lines, arcs and shapes, not listed

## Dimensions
3346.45,4921.25 to 3346.45,0 on M2 Board Dimensions
0,5196.85 to 3346.45,5196.85 on M2 Board Dimensions
0,5196.85 to 0,-275.59 on M2 Board Dimensions
2679.85,3666.96 to 5732,483.81 on M10 Fab Notes
3356.6,4933.7 to 3778.15,4932.7 on M2 Board Dimensions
